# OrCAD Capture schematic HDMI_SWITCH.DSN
size A
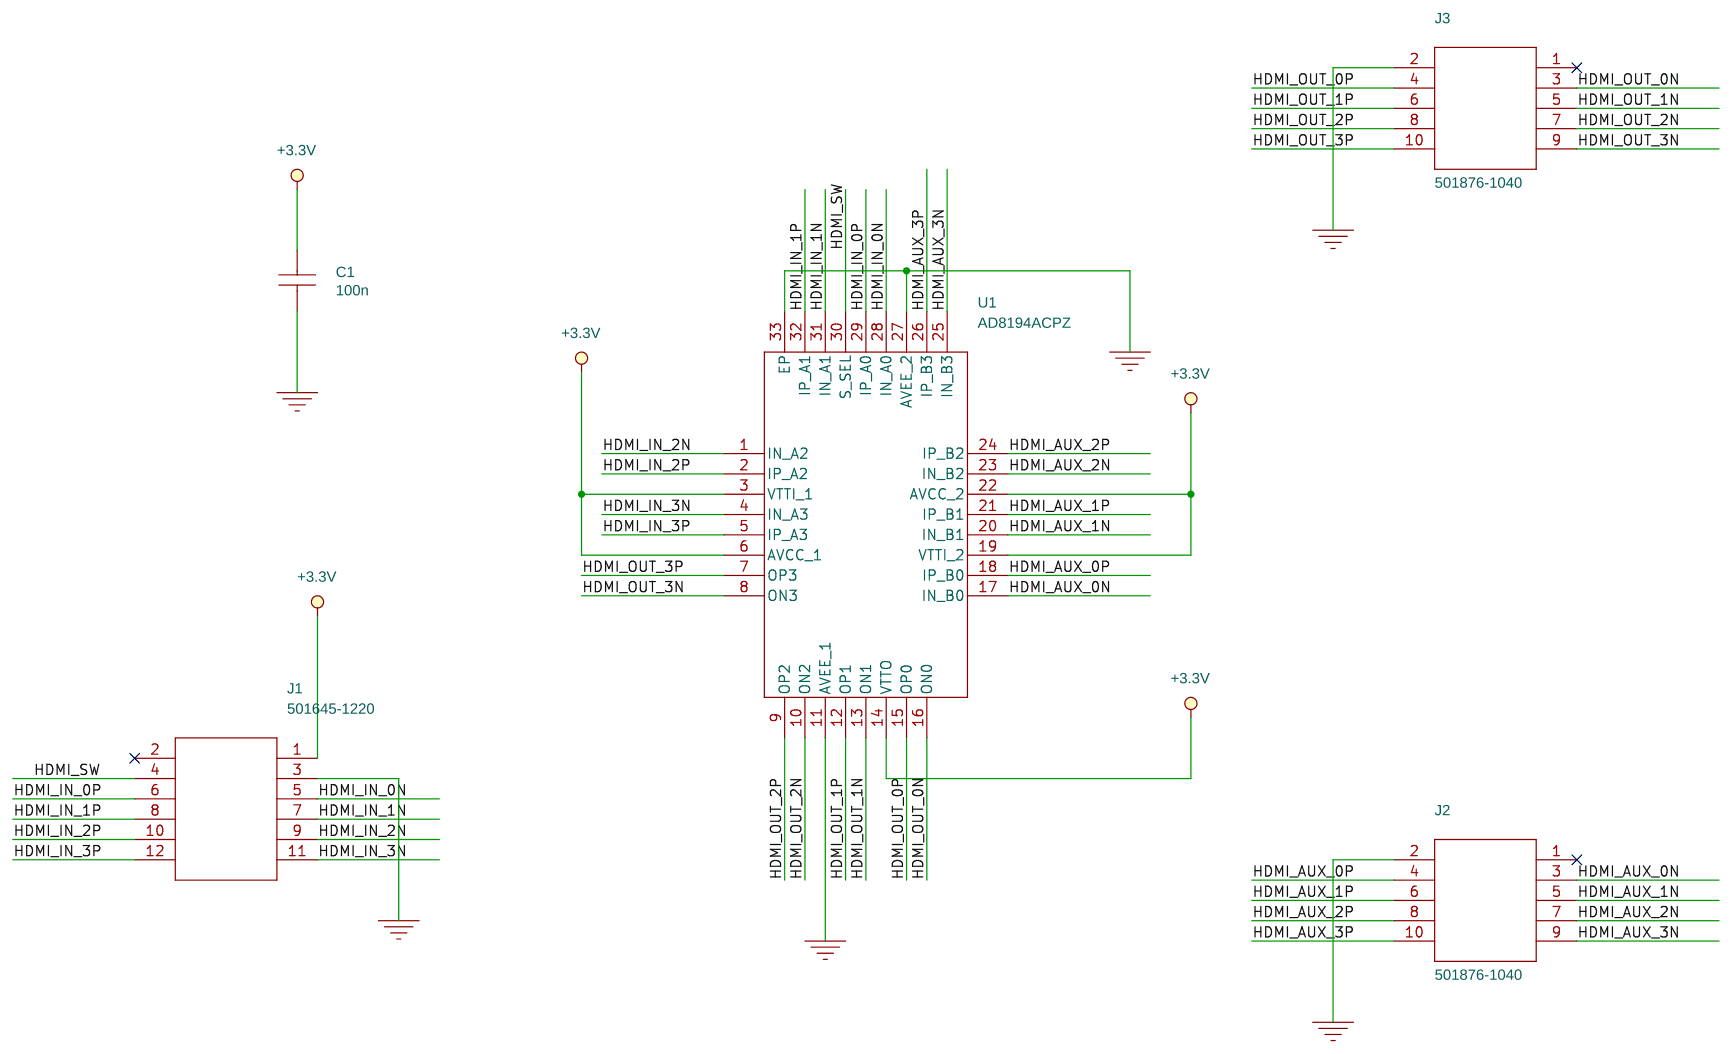
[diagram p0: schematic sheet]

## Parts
C1  100n  [0402-CAP]
J1  501645-1220  [5016451220]
J2  501876-1040  [5018761040]
J3  501876-1040  [5018761040]
U1  AD8194ACPZ  [QFN50P500X500X100-33N-D]

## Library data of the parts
C1 = CAP_NP
J1 = 501645-1220: DataSheet URL: https://www.molex.com/pdm_docs/sd/5016451220_sd.pdf; Have 3D: 1; Have Footprint: 1; Have Symbol: 1; Image URL: https://g.componentsearchengine.com/Thumbnails/1/501645-1220.jpg; Manufacturer Name: Molex; Part Description: MOLEX - 501645-1220. - CONNECTOR, HEADER, 12POS, 2ROW, 2MM; Source Id: SamacSys; Status: <Status>
J2 J3 = 501876-1040: DataSheet URL: http://www.farnell.com/datasheets/2697009.pdf; Have 3D: 1; Have Footprint: 1; Have Symbol: 1; Image URL: https://g.componentsearchengine.com/Thumbnails/3/501876-1040.jpg; Manufacturer Name: Molex; Part Description: MOLEX - 501876-1040 - CONNECTOR, HEADER, 10POS, 2ROW, 2MM; Source Id: SamacSys; Status: <Status>
U1 = AD8194ACPZ: DataSheet URL: https://datasheet.datasheetarchive.com/originals/distributors/Datasheets-SFU1/DSASFU10003782.pdf; Have 3D: 1; Have Footprint: 1; Have Symbol: 1; Image URL: https://g.componentsearchengine.com/Thumbnails/1/AD8194ACPZ.jpg; Manufacturer Name: Analog Devices; Part Description: AD8194ACPZ, Video Switch 32-Pin LFCSP EP; Source Id: SamacSys; Status: <Status>

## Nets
+3.3V: C1.1 J1.1 U1.3(VTTI_1) U1.6(AVCC_1) U1.14(VTTO) U1.19(VTTI_2) U1.22(AVCC_2)
0: C1.2 J1.3 J2.2 J3.2 U1.11(AVEE_1) U1.27(AVEE_2) U1.33(EP)
HDMI_AUX_0N: J2.3 U1.17(IN_B0)
HDMI_AUX_0P: J2.4 U1.18(IP_B0)
HDMI_AUX_1N: J2.5 U1.20(IN_B1)
HDMI_AUX_1P: J2.6 U1.21(IP_B1)
HDMI_AUX_2N: J2.7 U1.23(IN_B2)
HDMI_AUX_2P: J2.8 U1.24(IP_B2)
HDMI_AUX_3N: J2.9 U1.25(IN_B3)
HDMI_AUX_3P: J2.10 U1.26(IP_B3)
HDMI_IN_0N: J1.5 U1.28(IN_A0)
HDMI_IN_0P: J1.6 U1.29(IP_A0)
HDMI_IN_1N: J1.7 U1.31(IN_A1)
HDMI_IN_1P: J1.8 U1.32(IP_A1)
HDMI_IN_2N: J1.9 U1.1(IN_A2)
HDMI_IN_2P: J1.10 U1.2(IP_A2)
HDMI_IN_3N: J1.11 U1.4(IN_A3)
HDMI_IN_3P: J1.12 U1.5(IP_A3)
HDMI_OUT_0N: J3.3 U1.16(ON0)
HDMI_OUT_0P: J3.4 U1.15(OP0)
HDMI_OUT_1N: J3.5 U1.13(ON1)
HDMI_OUT_1P: J3.6 U1.12(OP1)
HDMI_OUT_2N: J3.7 U1.10(ON2)
HDMI_OUT_2P: J3.8 U1.9(OP2)
HDMI_OUT_3N: J3.9 U1.8(ON3)
HDMI_OUT_3P: J3.10 U1.7(OP3)
HDMI_SW: J1.4 U1.30(S_SEL)

Not connected (* = marked no-connect by the designer): J1 2*; J2 1*; J3 1*
